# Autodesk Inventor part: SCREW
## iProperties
Created: 2006-07
Part Number: SCREW
Material: Steel, High Strength Low Alloy
Document SubType Name: Modeling
Designer: rollin42
Density: 7.84 g/cm^3
Author: rollin42
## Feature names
1. Extrusion1
2. Extrusion2
3. Coil1
4. Extrusion3
5. Revolution1
6. Hole1
